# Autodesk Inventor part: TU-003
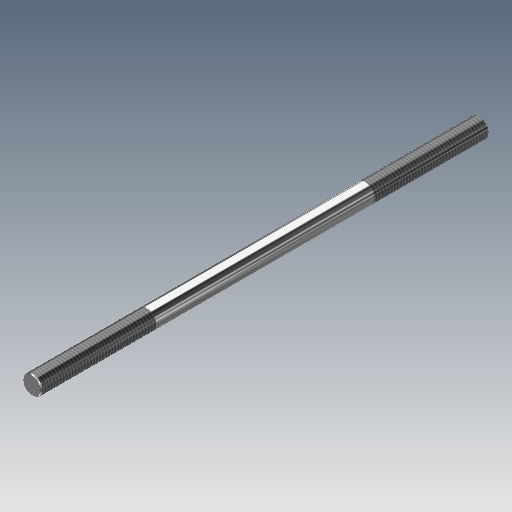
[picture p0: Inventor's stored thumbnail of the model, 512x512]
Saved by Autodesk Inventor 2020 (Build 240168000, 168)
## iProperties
Created: 2002-07
Part Number: TU-003
Document SubType Name: Modeling
Designer: PN
Description: M5 x 120 Threaded Rod
Mass: 18.7131 g
Surface Area: 18.8805 cm^2
Volume: 2.31598 cm^3
Density: 8.08 g/cm^3
Material: Stainless Steel
Appearance: Chrome - Polished
Control State: 0
Master: False
Checked Out: False
Shininess: 64.0
Angle Display Precision: 2
Document Length Units: 11269
Document Angle Units: 11279
Document Time Units: 11290
Document Mass Units: 11283
Document Length Units Precision: 3
Document Angle Units Precision: 2
Compacted: True
Density: 0.0
Volumn: 0.0
Area: 0.0
PropertySet Name: Model Information
Author: PN
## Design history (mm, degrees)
sketch "Sketch1"
  geometry: C1 r 2.5 at (0, 0); 1 further point
  constraints: 1 centre point, 1 coincident
  dimensions: "d0" = 5 diameter of C1
extrude "Extrusion1" new body sketch "Sketch1" stored distance "d1" = 118; taper "d2" = 0 deg
chamfer "Chamfer1" distance "d3" = 0.25; stored, may be unused: second distance "d4" = 0.25, angle "d7" = 45 deg
thread "Thread1" dims "d5" = 30, "d6" = 0
thread "Thread2" dims "d8" = 30, "d9" = 0
body "Solid1"
